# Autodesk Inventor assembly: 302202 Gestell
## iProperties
Created: 2006-12
Part Number: 302202 Gestell
Cost Center: 0 kg
Document SubType Name: Assembly
Designer: Martin
Authority: 0 mm^3
Mass: 50274.7 g
Surface Area: 13050.9 cm^2
Volume: 6951.87 cm^3
Density: 7.23183 g/cm^3
SaveDate: 2004-08-02
SaveTime: 16:43
TotalMass: 0 kg
TotalVolume: 0 mm^3
Author: Martin
